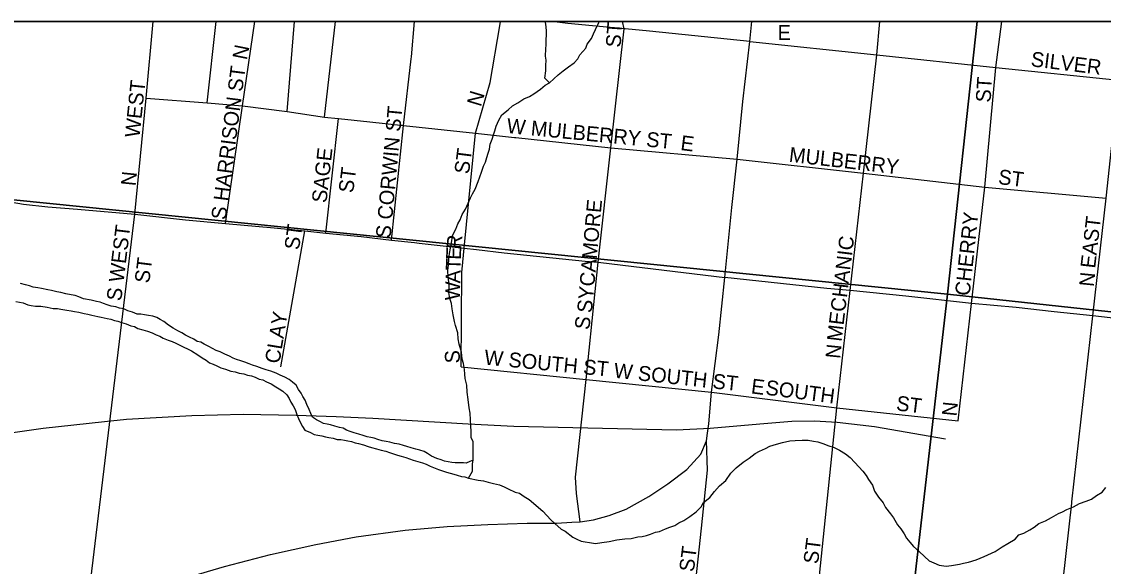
# Model space of a CAD drawing. Extents: x 0 to 34, y -4 to 22.
# Drawn here: x 5.5242 to 6.0097, y 20.6558 to 20.9 of the extents above; entities that cross this region are included whole.
import ezdxf

# ---------------------------------------------------------------- set-up
doc = ezdxf.new("R2010")
doc.units = 0
for name, color, linetype in [('GM_X_City_Street', 7, 'Continuous'), ('GM_X_City_Street_Text', 7, 'Continuous'), ('GM_X_Corporation', 7, 'Continuous'), ('GM_X_Minor_River', 7, 'Continuous'), ('GM_X_Rail_Line', 7, 'Continuous'), ('GM_X_Section', 7, 'Continuous'), ('GM_X_State_Route', 7, 'Continuous'), ('GM_X_US_Route', 7, 'Continuous'), ('SH_Data', 7, 'Continuous'), ('SN_P_Text', 7, 'Continuous')]:
    doc.layers.add(name, color=color, linetype=linetype)

msp = doc.modelspace()

# ---------------------------------------------------------------- linework, layer by layer
at = {"layer": 'GM_X_City_Street'}
for p, q in [((5.60746, 20.86363), (5.6115, 20.9)), ((5.62331, 20.86225), (5.62888, 20.9)), ((5.6433, 20.85975), (5.64671, 20.9)), ((5.66013, 20.85719), (5.66509, 20.9)), ((5.69909, 20.88416), (5.70051, 20.9)), ((5.73878, 20.8981), (5.73911, 20.9)), ((5.79454, 20.8968), (5.79387, 20.9)), ((5.90796, 20.88511), (5.90935, 20.9))]:
    msp.add_line(p, q, dxfattribs=at)
for points in [[(5.57495, 20.81363), (5.58005, 20.86566), (5.58321, 20.9)], [(5.95639, 20.82582), (5.96146, 20.8795), (5.96405, 20.9)], [(5.72793, 20.85002), (5.73445, 20.87265), (5.73878, 20.8981)], [(5.77758, 20.73963), (5.78287, 20.79211), (5.78855, 20.84343), (5.79454, 20.8968)], [(5.85103, 20.89108), (5.90796, 20.88511)], [(5.89005, 20.72688), (5.896, 20.7795), (5.90197, 20.83213), (5.90796, 20.88511)], [(5.90796, 20.88511), (5.96146, 20.8795), (6.01666, 20.8737), (6.07061, 20.86804), (6.1244, 20.8624), (6.20169, 20.85381)], [(5.69563, 20.85343), (5.69901, 20.8833), (5.69909, 20.88416)], [(6.00497, 20.76811), (6.01095, 20.82092), (6.01666, 20.8737)], [(5.58005, 20.86566), (5.60746, 20.86363), (5.62331, 20.86225), (5.6433, 20.85975), (5.66013, 20.85719), (5.66631, 20.85654)], [(5.61565, 20.80956), (5.62331, 20.86225)], [(5.66066, 20.80523), (5.66642, 20.85653)], [(5.66631, 20.85654), (5.66642, 20.85653), (5.68044, 20.85504), (5.69563, 20.85343), (5.72793, 20.85002), (5.74542, 20.84813)], [(5.69014, 20.80207), (5.69563, 20.85343)], [(5.72193, 20.78905), (5.72286, 20.79844), (5.72793, 20.85002)], [(5.74542, 20.84813), (5.74603, 20.84806), (5.78855, 20.84343)], [(5.78855, 20.84343), (5.84531, 20.83835), (5.90197, 20.83213), (5.95639, 20.82582)], [(5.94448, 20.72105), (5.95053, 20.77363), (5.95639, 20.82582)], [(5.95639, 20.82582), (5.95639, 20.82582), (6.01095, 20.82092)], [(5.5538, 20.63751), (5.57495, 20.81363)], [(5.64058, 20.74529), (5.65123, 20.80622)], [(5.72139, 20.7453), (5.7218, 20.7877), (5.72193, 20.78905)], [(5.99551, 20.68466), (6.00497, 20.76811)], [(5.72139, 20.7453), (5.77758, 20.73963)], [(5.77488, 20.67572), (5.77327, 20.68838), (5.77274, 20.69578), (5.77758, 20.73963)], [(5.77758, 20.73963), (5.83383, 20.73384)], [(5.83383, 20.73384), (5.89005, 20.72688)], [(5.87085, 20.54096), (5.87632, 20.59383), (5.89005, 20.72688)], [(5.89005, 20.72688), (5.94448, 20.72105)], [(5.81676, 20.5567), (5.81684, 20.55752), (5.82937, 20.67297), (5.83201, 20.69895), (5.83156, 20.71202)], [(5.97144, 20.47803), (5.975, 20.50177), (5.97786, 20.52963), (5.98379, 20.58059), (5.99544, 20.68411), (5.99551, 20.68466)]]:
    msp.add_lwpolyline(points, dxfattribs=at)
at = {"layer": 'GM_X_Corporation'}
msp.add_lwpolyline([(6.71482, 20.9), (4.7312, 20.9)], dxfattribs=at)
at = {"layer": 'GM_X_Minor_River'}
for points in [[(5.72689, 20.70332), (5.72689, 20.7116), (5.72588, 20.71351), (5.72597, 20.71618), (5.72579, 20.71885), (5.72561, 20.72153), (5.72544, 20.72448), (5.72498, 20.7269), (5.72457, 20.73065), (5.72414, 20.73387), (5.72398, 20.73708), (5.72327, 20.74004), (5.72307, 20.74192), (5.72287, 20.74407), (5.72242, 20.74675), (5.72195, 20.74864), (5.72152, 20.75186), (5.72056, 20.75536), (5.7201, 20.75778), (5.71992, 20.76046), (5.71896, 20.7637), (5.71848, 20.76558), (5.71778, 20.76854), (5.71733, 20.77123), (5.71714, 20.77364), (5.71641, 20.7758), (5.71596, 20.77849), (5.71604, 20.78089), (5.71585, 20.7833), (5.71565, 20.78544), (5.71548, 20.78839), (5.71583, 20.79078), (5.71593, 20.79372), (5.71627, 20.79612), (5.71662, 20.79851), (5.71726, 20.8017), (5.71761, 20.80409), (5.71904, 20.80699), (5.71992, 20.80937), (5.72105, 20.8112), (5.72194, 20.81358), (5.72335, 20.81594), (5.72451, 20.81858), (5.72566, 20.82095), (5.72653, 20.82279), (5.72767, 20.8249), (5.72912, 20.82832), (5.7306, 20.83256), (5.73149, 20.8352), (5.73235, 20.83705), (5.73296, 20.83916), (5.73355, 20.84102), (5.73415, 20.84287), (5.73449, 20.845), (5.73537, 20.84738), (5.73597, 20.84923), (5.73656, 20.85108), (5.73717, 20.8532), (5.73833, 20.85584), (5.73974, 20.8582), (5.7425, 20.86052), (5.74443, 20.86233), (5.74689, 20.86359), (5.74963, 20.86538), (5.75207, 20.86637), (5.75399, 20.86765), (5.757, 20.86969), (5.7592, 20.87149), (5.76111, 20.8725), (5.76305, 20.87432), (5.76498, 20.87613), (5.76718, 20.87793), (5.76965, 20.87972), (5.77212, 20.88152), (5.77379, 20.88334), (5.77465, 20.88518), (5.77743, 20.88804), (5.77802, 20.88989), (5.77998, 20.8925), (5.78086, 20.89461), (5.78172, 20.89646), (5.78317, 20.89962), (5.78331, 20.9)], [(5.76111, 20.8725), (5.75904, 20.87471), (5.75941, 20.8779), (5.75949, 20.8803), (5.75957, 20.88271), (5.75936, 20.88458), (5.75947, 20.88779), (5.75953, 20.88966), (5.75961, 20.89206), (5.75967, 20.89393), (5.75973, 20.8958), (5.75953, 20.89768), (5.75933, 20.89982), (5.75931, 20.9)], [(5.65965, 20.71982), (5.65807, 20.72067), (5.65649, 20.72152), (5.65465, 20.72265), (5.6539, 20.72428), (5.65316, 20.72617), (5.65216, 20.72834), (5.65142, 20.73023), (5.6504, 20.73187), (5.64965, 20.73349), (5.64837, 20.73514), (5.64736, 20.73704), (5.64579, 20.73842), (5.64422, 20.73954), (5.64238, 20.74067), (5.64027, 20.74153), (5.63842, 20.74239), (5.63604, 20.74327), (5.63392, 20.74387), (5.63206, 20.74446), (5.62968, 20.74533), (5.62782, 20.74593), (5.62623, 20.74651), (5.62439, 20.74737), (5.62253, 20.74796), (5.62067, 20.74855), (5.61909, 20.74914), (5.61751, 20.74999), (5.61539, 20.75085), (5.61329, 20.75199), (5.61143, 20.75258), (5.60985, 20.75343), (5.60827, 20.75428), (5.60617, 20.75541), (5.60459, 20.75626), (5.60299, 20.75658), (5.60142, 20.7577), (5.59957, 20.75856), (5.59772, 20.75942), (5.59615, 20.76053), (5.59431, 20.76139), (5.5922, 20.76252), (5.5901, 20.76393), (5.58801, 20.76559), (5.58643, 20.76644), (5.58486, 20.76729), (5.583, 20.76788), (5.58113, 20.76821), (5.57927, 20.76854), (5.57767, 20.76885), (5.57607, 20.7689), (5.57395, 20.76977), (5.57183, 20.77037), (5.56998, 20.77123), (5.56812, 20.77155), (5.56653, 20.77214), (5.5644, 20.77247), (5.56254, 20.77306), (5.56095, 20.77364), (5.55936, 20.77423), (5.55777, 20.77454), (5.55538, 20.77515), (5.55191, 20.77579), (5.5498, 20.77666), (5.54821, 20.77724), (5.54635, 20.77757), (5.54395, 20.77791), (5.54182, 20.77851), (5.53996, 20.77883), (5.53757, 20.77944), (5.53597, 20.77976), (5.53304, 20.78038), (5.53145, 20.7807), (5.52931, 20.78103), (5.52773, 20.78162), (5.52586, 20.78194), (5.52374, 20.78254)], [(5.5216, 20.77459), (5.5248, 20.77396), (5.52691, 20.77309), (5.52851, 20.77277), (5.53037, 20.77245), (5.53278, 20.77237), (5.53571, 20.77202), (5.53837, 20.7714), (5.54025, 20.77134), (5.54184, 20.77103), (5.54451, 20.77068), (5.54638, 20.77035), (5.54797, 20.77004), (5.54984, 20.76971), (5.55223, 20.7691), (5.55383, 20.76878), (5.55569, 20.76846), (5.55835, 20.76784), (5.55995, 20.76753), (5.56261, 20.76691), (5.5642, 20.76659), (5.56579, 20.76601), (5.56739, 20.76569), (5.56898, 20.76511), (5.5711, 20.76451), (5.57321, 20.76364), (5.57481, 20.76333), (5.57639, 20.76248), (5.57851, 20.76188), (5.58064, 20.76128), (5.58275, 20.76041), (5.5846, 20.75955), (5.58619, 20.75897), (5.58777, 20.75812), (5.58988, 20.75725), (5.59174, 20.75666), (5.59332, 20.75581), (5.59517, 20.75495), (5.59701, 20.75409), (5.59859, 20.75324), (5.60044, 20.75238), (5.60333, 20.75069), (5.60516, 20.7493), (5.607, 20.74817), (5.60857, 20.74705), (5.61016, 20.74647), (5.61174, 20.74562), (5.61359, 20.74476), (5.61571, 20.74416), (5.61809, 20.74329), (5.61996, 20.74296), (5.62181, 20.74237), (5.62394, 20.74204), (5.62553, 20.74145), (5.6274, 20.74113), (5.62899, 20.74054), (5.63083, 20.73969), (5.63243, 20.73937), (5.63401, 20.73852), (5.63612, 20.73765), (5.63822, 20.73625), (5.6398, 20.7354), (5.64137, 20.73428), (5.64319, 20.73262), (5.64421, 20.73099), (5.64496, 20.72936), (5.64598, 20.72773), (5.647, 20.72609), (5.64773, 20.72393), (5.64847, 20.72204), (5.64922, 20.72041), (5.65023, 20.71851), (5.65125, 20.71688), (5.65389, 20.71572), (5.65547, 20.71487), (5.65707, 20.71456), (5.65893, 20.71423), (5.66053, 20.71392), (5.66212, 20.7136), (5.66399, 20.71328), (5.66584, 20.71268), (5.66745, 20.71264), (5.66905, 20.71232), (5.67064, 20.712), (5.67224, 20.71169), (5.67383, 20.7111), (5.67543, 20.71079), (5.67755, 20.71019), (5.67967, 20.70958), (5.68126, 20.709), (5.68339, 20.7084), (5.68551, 20.7078), (5.68764, 20.70747), (5.68923, 20.70688)], [(5.72256, 20.70212), (5.71881, 20.70223), (5.71721, 20.70228), (5.71561, 20.7026), (5.71401, 20.70291), (5.71243, 20.7035), (5.71057, 20.70409), (5.7082, 20.70523), (5.70636, 20.70636), (5.70478, 20.70721), (5.70292, 20.7078), (5.70107, 20.70839), (5.69894, 20.70899), (5.69709, 20.70958), (5.69549, 20.7099), (5.69363, 20.71049), (5.6915, 20.71082), (5.68938, 20.71142), (5.68778, 20.71174), (5.68592, 20.71206), (5.68406, 20.71266), (5.68247, 20.71324), (5.68088, 20.71356), (5.67928, 20.71387), (5.67742, 20.71447), (5.67557, 20.71506), (5.67344, 20.71566), (5.67159, 20.71625), (5.67, 20.71683), (5.66842, 20.71768), (5.66682, 20.718), (5.6647, 20.7186), (5.66284, 20.71919), (5.66125, 20.71951), (5.65965, 20.71982)], [(5.72475, 20.69537), (5.72901, 20.69444), (5.73141, 20.69409), (5.73353, 20.69349), (5.73592, 20.69289), (5.73858, 20.69227), (5.74069, 20.6914), (5.74254, 20.69054), (5.74571, 20.68911), (5.74757, 20.68852), (5.74966, 20.68712), (5.75203, 20.68571), (5.75385, 20.68405), (5.7562, 20.68211), (5.75802, 20.68045), (5.75983, 20.67852), (5.76164, 20.67659), (5.76346, 20.67493), (5.76633, 20.67244), (5.76817, 20.67158), (5.77157, 20.66881), (5.77341, 20.66795), (5.77526, 20.66709), (5.77712, 20.66676), (5.77899, 20.66644), (5.78166, 20.66609), (5.78462, 20.66653), (5.78785, 20.66697), (5.79135, 20.66766), (5.79485, 20.66809), (5.7978, 20.66826), (5.80077, 20.66897), (5.80265, 20.66918), (5.80455, 20.66966), (5.80644, 20.67014), (5.80861, 20.67114), (5.81049, 20.67135), (5.81321, 20.6726), (5.81511, 20.67334), (5.81728, 20.67408), (5.8192, 20.67536), (5.82138, 20.67636), (5.82411, 20.67814), (5.82686, 20.6802), (5.82908, 20.68253), (5.83021, 20.68437), (5.83297, 20.68669), (5.8352, 20.68929), (5.83743, 20.6919), (5.84018, 20.69422), (5.84244, 20.69762), (5.84492, 20.69995), (5.84795, 20.70253), (5.85069, 20.70432), (5.85344, 20.70637), (5.85535, 20.70738), (5.85807, 20.70863), (5.85998, 20.70964), (5.86296, 20.71062), (5.86566, 20.71134), (5.8689, 20.71204), (5.87131, 20.71223), (5.87453, 20.7124), (5.87721, 20.71232), (5.87961, 20.71198), (5.88148, 20.71165), (5.88413, 20.71077), (5.88597, 20.70991), (5.88889, 20.70902), (5.89126, 20.70788), (5.89389, 20.70619), (5.89598, 20.70452), (5.89805, 20.70232), (5.89986, 20.7004), (5.90167, 20.69847), (5.90321, 20.69655), (5.90422, 20.69465), (5.90602, 20.69219), (5.907, 20.68949), (5.90879, 20.68676), (5.91085, 20.68429), (5.91185, 20.68212), (5.91417, 20.67938), (5.91545, 20.67747), (5.91722, 20.67447), (5.91877, 20.67255), (5.92031, 20.67037), (5.92131, 20.66847), (5.92286, 20.66655), (5.9244, 20.66463), (5.92701, 20.66241), (5.92935, 20.6602), (5.93143, 20.65827), (5.93354, 20.6574), (5.93591, 20.65626), (5.93912, 20.65589), (5.94153, 20.65609), (5.94504, 20.65678), (5.94693, 20.65726), (5.94909, 20.65772), (5.95261, 20.65868)], [(5.68923, 20.70688), (5.69109, 20.70629), (5.69294, 20.7057), (5.69453, 20.70512), (5.69665, 20.70452), (5.69824, 20.70394), (5.69983, 20.70335), (5.70195, 20.70275), (5.70408, 20.70215), (5.70567, 20.70157), (5.70751, 20.70071), (5.7091, 20.70013), (5.71121, 20.69926), (5.71307, 20.69867), (5.71493, 20.69808), (5.71652, 20.69749), (5.71811, 20.69718), (5.7197, 20.69659), (5.72156, 20.696), (5.72316, 20.69595), (5.72475, 20.69537)], [(5.72475, 20.69537), (5.72646, 20.69852), (5.72651, 20.70012), (5.72657, 20.70173), (5.72689, 20.70332), (5.72526, 20.70284), (5.72363, 20.70208), (5.72256, 20.70212)], [(5.95261, 20.65868), (5.95614, 20.66018), (5.96103, 20.66243), (5.96431, 20.66447), (5.96678, 20.666), (5.97006, 20.66804), (5.97173, 20.66986), (5.97389, 20.67059), (5.97662, 20.67211), (5.97854, 20.67339), (5.98073, 20.67492), (5.98372, 20.67617), (5.98645, 20.67768), (5.98945, 20.67946), (5.99135, 20.68021), (5.99326, 20.68122), (5.99625, 20.68246), (5.99898, 20.68398), (6.00196, 20.68496), (6.0044, 20.68595), (6.0066, 20.68749), (6.00906, 20.68901), (6.01073, 20.6911)]]:
    msp.add_lwpolyline(points, dxfattribs=at)
at = {"layer": 'GM_X_Rail_Line'}
for points in [[(5.83313, 20.71763), (5.81812, 20.71685), (5.74509, 20.71848), (5.72465, 20.71958), (5.6818, 20.72209), (5.66529, 20.72275), (5.64736, 20.7234), (5.62364, 20.72384), (5.60057, 20.7233), (5.57127, 20.72155), (5.56133, 20.72056), (5.53389, 20.71761), (5.50328, 20.71324), (5.47802, 20.70865), (5.45408, 20.70329), (5.43277, 20.69793), (5.40893, 20.69126), (5.38434, 20.68328), (5.36083, 20.67498), (5.34465, 20.66863), (5.32027, 20.65836), (5.29415, 20.64644), (5.27677, 20.63759)], [(5.9388, 20.71275), (5.907, 20.71827), (5.89016, 20.72023), (5.88, 20.72089), (5.86983, 20.72078), (5.85551, 20.71958), (5.83313, 20.71763)]]:
    msp.add_lwpolyline(points, dxfattribs=at)
at = {"layer": 'GM_X_Section'}
for points in [[(5.95301, 20.9), (5.22815, 20.9), (5.22276, 20.85012), (5.93966, 20.77778)], [(6.64773, 20.9), (5.95301, 20.9), (5.93966, 20.77778), (6.62746, 20.70359)], [(5.90509, 20.47803), (5.93966, 20.77778), (5.22276, 20.85012), (5.14968, 20.19347), (5.54309, 20.15662), (5.54309, 20.47803)], [(5.90509, 20.47803), (6.60508, 20.47803), (6.62746, 20.70359), (5.93966, 20.77778)]]:
    msp.add_lwpolyline(points, close=True, dxfattribs=at)
at = {"layer": 'GM_X_State_Route'}
for points in [[(5.79499, 20.89675), (5.79454, 20.8968), (5.76938, 20.89922), (5.7622, 20.9)], [(5.85103, 20.89108), (5.80599, 20.89569), (5.79499, 20.89675)], [(5.4778, 20.83141), (5.47867, 20.83108), (5.48559, 20.82846), (5.49543, 20.82503), (5.50062, 20.82347), (5.50593, 20.822), (5.5117, 20.82066), (5.51906, 20.81927), (5.52508, 20.81824), (5.53596, 20.817), (5.54932, 20.81598), (5.57495, 20.81363), (5.5978, 20.81116), (5.61565, 20.80956), (5.6375, 20.80752), (5.65123, 20.80622), (5.66066, 20.80523), (5.67659, 20.80367), (5.69014, 20.80207), (5.70049, 20.80092)], [(5.70049, 20.80092), (5.70256, 20.80069), (5.72286, 20.79844), (5.72835, 20.79779)], [(5.72835, 20.79779), (5.74074, 20.79633), (5.77715, 20.79268)], [(5.77715, 20.79268), (5.78287, 20.79211), (5.78413, 20.79196)], [(5.78413, 20.79196), (5.83981, 20.78525)], [(6.03216, 20.76489), (6.00497, 20.76811), (5.98754, 20.76987), (5.97053, 20.77177), (5.95053, 20.77363), (5.92097, 20.77688), (5.896, 20.7795), (5.88552, 20.78038), (5.83981, 20.78525)]]:
    msp.add_lwpolyline(points, dxfattribs=at)
at = {"layer": 'GM_X_US_Route'}
msp.add_line((5.85103, 20.89108), (5.85185, 20.9), dxfattribs=at)
for points in [[(5.83981, 20.78525), (5.84296, 20.81668), (5.84531, 20.83835), (5.84788, 20.86418), (5.85103, 20.89108)], [(5.83201, 20.71552), (5.83254, 20.71965), (5.83383, 20.73384), (5.83715, 20.75959), (5.83981, 20.78525)], [(5.77106, 20.67552), (5.77488, 20.67572), (5.78081, 20.67661), (5.78782, 20.67859), (5.79554, 20.68136), (5.80574, 20.68709), (5.81412, 20.69283), (5.82273, 20.69926), (5.829, 20.70605), (5.83156, 20.71202), (5.83201, 20.71552)], [(5.55111, 20.63666), (5.5538, 20.63751), (5.58098, 20.64559), (5.59846, 20.65073), (5.61522, 20.65567), (5.6359, 20.6611), (5.65625, 20.66559), (5.67437, 20.66895), (5.69625, 20.67196), (5.71512, 20.67364), (5.73335, 20.6745), (5.75105, 20.67516), (5.76421, 20.67517), (5.77106, 20.67552)]]:
    msp.add_lwpolyline(points, dxfattribs=at)
at = {"layer": 'SH_Data'}
msp.add_line((2.1, 20.9), (8.9, 20.9), dxfattribs=at)
at = {"layer": 'SN_P_Text'}
msp.add_lwpolyline([(8.9, 14.1), (8.9, 20.9), (2.1, 20.9), (2.1, 14.1)], close=True, dxfattribs=at)

# ---------------------------------------------------------------- texts
at = {"layer": 'GM_X_City_Street_Text'}
for s, height, rotation, p in [('ST', 0.006667, 86.1879, (5.79299, 20.88825)), ('E', 0.00667, 0, (5.86347, 20.89177)), ('N', 0.00667, 78.6943, (5.62523, 20.88255)), ('SILVER', 0.006667, 353.0189, (5.97685, 20.88003)), ('S HARRISON ST', 0.0066667, 82.6652, (5.61583, 20.81089)), ('WEST', 0.006667, 84.0556, (5.5771, 20.8478)), ('ST', 0.006667, 86.4118, (5.95902, 20.86361)), ('N', 0.00667, 73.2927, (5.73027, 20.86154)), ('S CORWIN ST', 0.0066667, 84.744, (5.68974, 20.80263)), ('W MULBERRY ST', 0.0066667, 354.4415, (5.74165, 20.85011)), ('E', 0.00667, 352.8783, (5.81963, 20.84248)), ('SAGE', 0.006667, 83.6571, (5.661, 20.8185)), ('ST', 0.006667, 82.8783, (5.72495, 20.83142)), ('MULBERRY', 0.006667, 353.4424, (5.86833, 20.8372)), ('N', 0.00667, 84.2916, (5.57534, 20.82611)), ('ST', 0.006667, 82.8666, (5.67297, 20.82295)), ('ST', 0.006667, 352.8649, (5.96219, 20.82723)), ('SYCAMORE', 0.006667, 84.8056, (5.78009, 20.76919)), ('CHERRY', 0.006667, 83.9456, (5.94964, 20.77684)), ('EAST', 0.006667, 83.4775, (6.00596, 20.78917)), ('S WEST', 0.006667, 83.0183, (5.56889, 20.77451)), ('ST', 0.006667, 82.3949, (5.64868, 20.7974)), ('R', 0.00667, 85.2101, (5.72146, 20.79774)), ('MECHANIC', 0.006667, 83.0663, (5.89215, 20.75632)), ('E', 0.00667, 87.978, (5.7213, 20.79314)), ('ST', 0.006667, 82.88, (5.58145, 20.78248)), ('T', 0.00667, 88.5242, (5.72118, 20.78846)), ('A', 0.00667, 88.5357, (5.72103, 20.7826)), ('W', 0.00667, 88.5372, (5.72083, 20.77497)), ('N', 0.00667, 84.2916, (6.00537, 20.78094)), ('CLAY', 0.006667, 80.7879, (5.63989, 20.7464)), ('S', 0.00667, 82.8783, (5.77892, 20.76161)), ('N', 0.00667, 84.2916, (5.89156, 20.74867)), ('S', 0.00667, 90, (5.72083, 20.74678)), ('W SOUTH ST', 0.006667, 354.4949, (5.73159, 20.74628)), ('W SOUTH ST', 0.006667, 353.8122, (5.78969, 20.74041)), ('E', 0.00667, 352.8514, (5.85131, 20.73336)), ('SOUTH', 0.006667, 352.5729, (5.85777, 20.73278)), ('ST', 0.006667, 352.8649, (5.91643, 20.72574)), ('N', 0.00667, 84.2937, (5.94377, 20.72285)), ('ST', 0.006667, 82.8649, (5.88159, 20.65659)), ('ST', 0.006667, 82.88, (5.82585, 20.65307))]:
    msp.add_text(s, height=height, rotation=rotation, dxfattribs=at).set_placement(p)

doc.saveas('drawing.dxf')
